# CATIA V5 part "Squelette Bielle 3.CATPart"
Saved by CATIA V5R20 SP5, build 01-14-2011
Part number: Squelette Bielle 3
Bounding box of the stored display mesh (mm): x -200 to 0, y -250 to -250, z -50 to 10
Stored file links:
  U:\CFAO\Thinkmotion\Squelette Bielle 3.CATPart
  U:\CFAO\Thinkmotion\Bras Articule.CATProduct
  U:\CFAO\Thinkmotion\Squelette general.CATPart
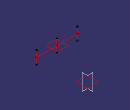
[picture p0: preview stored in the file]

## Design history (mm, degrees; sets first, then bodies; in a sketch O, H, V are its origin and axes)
Set1
  Line1: type PtPt, FirstPoint Point1, SecondPoint Point2
  Line2: type PtPt, FirstPoint Point3, SecondPoint Point2
  Line3: type Normal, RefPoint Point3, RefSkin Plane2, Start -30, End 30
  Line4: type Normal, RefPoint Point1, RefSkin Plane2, Start -30, End 30
  Line5: type Normal, RefPoint Point2, RefSkin Plane2, Start -30, End 30
  Plane1: type OffsetPt, RefPlane xy-plane, RefPoint Point2
Set2
  Point1 to Point3: linked copy from another document
  Plane2: linked copy from another document
Body1 (main body)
